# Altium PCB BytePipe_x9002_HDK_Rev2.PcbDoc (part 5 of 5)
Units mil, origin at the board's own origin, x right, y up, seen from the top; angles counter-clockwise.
Board outline 4250 x 4250 mil, 8 copper layers (Top Layer, L2-GND, L3-SIG, L4-GND, L5-PWR, L6-SIG, L7-GND, Bottom Layer), stack 63 mil thick; 296 components, 250 nets, 1198 pads, 2326 vias.
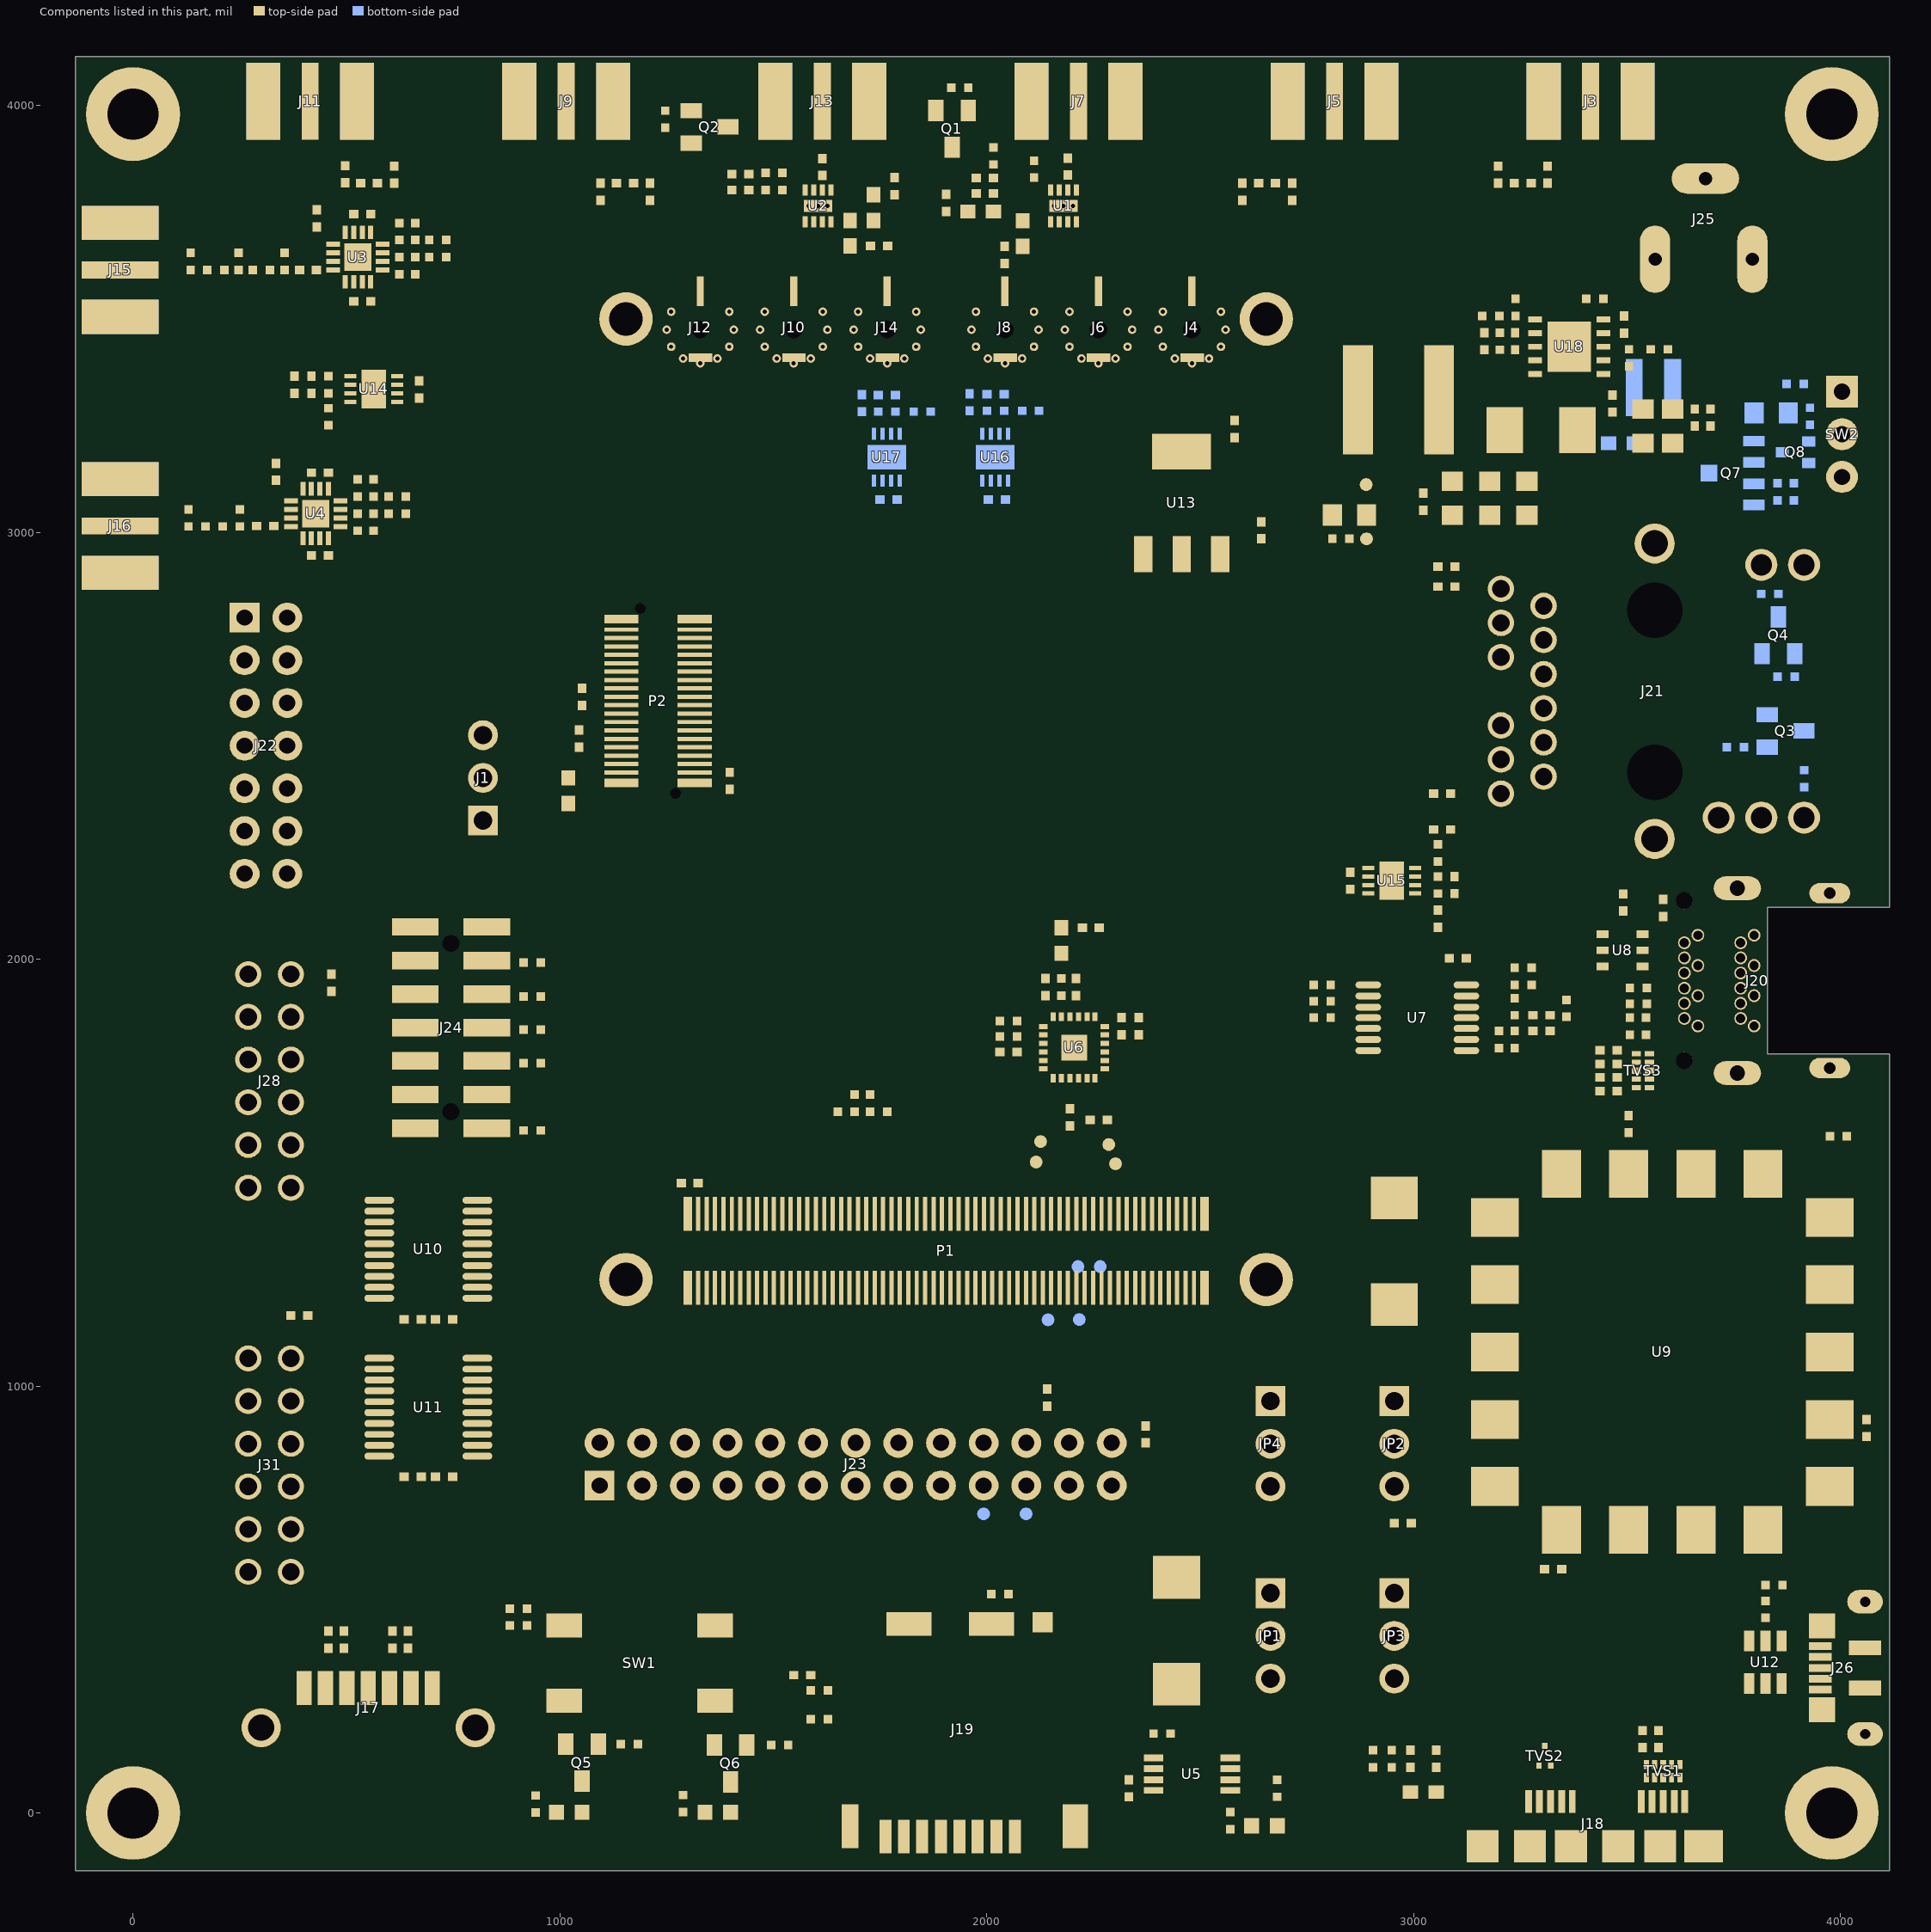
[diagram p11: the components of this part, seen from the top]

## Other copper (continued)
Bottom Layer:
  region net VCC5V0: 1761,3063.5 1761,3169 1731,3169 1731,3063.5
  region net VCC4V8_LNA1: 1757,3217 1757,3332 1735,3332 1735,3217
  region net VCC5V0: 2015,3069 2015,3169 1985,3169 1985,3069
  region net VCC4V8_LNA0: 2011,3217 2011,3334 1991,3334 1991,3217
  region net NetC73_2: 3607,3406 3711,3406 3711,3340 3643,3272 3607,3272
  text ".Layer_Name" at 2837.03,-378.88 h75

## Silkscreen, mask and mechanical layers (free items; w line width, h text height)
Top Overlay:
  drawing of 59 lines, arcs and shapes, not listed
  text "RX1B" at 3004,4048 h50
  text "RX2A" at 1248,4045 h50
  text "TX1" at 3604,4045 h50
  text "TX2" at 109,4040 h50
  text "RX1A" at 2408,4040 h50
  text "RX2B" at 658,4039 h50
  text "12V 2A" at 3659,3890 h40
  text "MCS" at -107,3803 h50
  text "ON" at 3771.5,3319.5 h40
  text "RF_CLK" at -117,3217 h50
  text "HDK_02" at 731.75,3188.74 h39.5 r270
  text "OFF" at 3770.5,3108.5 h40
  text "GND" at 83.5,2788.5 h30
  text "GND" at 438.5,2788.5 h30
  text "AUXADC_0" at -26.5,2689.5 h30
  text "AUXADC_1" at 436.5,2688.5 h30
  text "FAN" at 694.5,2600.5 h50
  text "GND" at 437.5,2586.5 h30
  text "GND" at 111.5,2584.5 h30
  text "RJ45 / ETHERNET" at 2853,2581 h35
  text "RFIC GPIO" at -94.5,2561 h50 r270
  text "AGPIO_2" at 432.5,2492.5 h30
  text "AGPIO_1" at 22.5,2484.5 h30
  text "AGPIO_4" at 433.5,2390.5 h30
  text "AGPIO_3" at 21.5,2385.5 h30
  text "AGPIO_6" at 432.5,2288.5 h30
  text "AGPIO_5" at 19.5,2285.5 h30
  text "DISPLAY" at 3832,2194 h50
  text "JTAG" at 657,2185 h50
  text "GND" at 433.5,2183.5 h30
  text "GND" at 112.5,2181.5 h30
  text "PMOD A" at -45.5,1309.5 h50
  text "UART1_RX" at 2005,935 h30 r90
  text "UART1_TX" at 1908,934 h30 r90
  text "GND" at 1107,932 h30 r90
  text "MIO43" at 1207.29,932 h30 r90
  text "MIO34" at 1307.57,932 h30 r90
  text "MIO42" at 1407.86,932 h30 r90
  text "MIO40" at 1508.14,932 h30 r90
  text "MIO44" at 1608.43,932 h30 r90
  text "MIO39" at 1708.71,932 h30 r90
  text "MIO41" at 1809,932 h30 r90
  text "GND" at 2208,932 h30 r90
  text "VCC3V3" at 2313,931 h30 r90
  text "VCC1V8" at 2107,930 h30 r90
  text "HOST" at 2882,923 h30 r90
  text "N/A" at 2585,922 h30 r90
  text "OTG" at 2587,747 h30 r90
  text "PWR SELECT" at 3089,707 h40 r90
  text "PS MIO" at 1023,704 h50 r90
  text "HRDW DETECT" at 2797,679 h40 r90
  text "OTG/ DEVICE" at 2881,639 h27 r90
  text "GND" at 2209,624 h30 r90
  text "MIO31" at 1307.5,597.78 h30 r90
  text "MIO36" at 1408,586.35 h30 r90
  text "MIO26" at 1609,586.35 h30 r90
  text "MIO32" at 1207,584.92 h30 r90
  text "MIO35" at 1508.5,584.92 h30 r90
  text "MIO33" at 1709.5,584.92 h30 r90
  text "MIO37" at 1810,584.92 h30 r90
  text "MIO38" at 1910.5,584.92 h30 r90
  text "GND" at 1107,577 h30 r90
  text "I2C_SCL" at 2105,563 h25 r90
  text "I2C_SDA" at 2006,561 h25 r90
  text "VCC3V3" at 2310,536 h30 r90
  text "SOM RESET" at 1066,505 h30
  text "OTG" at 2883,503 h30 r90
  text "SD CARD" at 2249,465 h50 r270
  text "JTAG Programmer" at 3246,423 h35
  text "OTG/ HOST" at 2592,419 h27 r90
  text "PMOD B" at -61.5,414.5 h50
  text "DEVICE" at 2591,241 h30 r90
  text "MODE SELECT" at 3091,223 h40 r90
  text "MODE SELECT" at 2798,220 h40 r90
  text "DEVICE/ HOST" at 2885,201 h27 r90
  text "SATA" at 154,117 h50 r90
  text "JTAG USB" at 3852,99 h50 r90
  text "PWR GOOD" at 1326,-103 h40
  text "PS DONE" at 956,-106 h40
  text "USB OVERCURRENT" at 2335,-110 h30
  text "USB  / 3.1-B" at 2916,-126 h45
  text ".Layer_Name" at 2837.03,-378.88 h75
Bottom Overlay:
  text ".Layer_Name" at 2837.03,-378.88 h75
Top Paste:
  text ".Layer_Name" at 2837.03,-378.88 h75
Bottom Paste:
  text ".Layer_Name" at 2837.03,-378.88 h75
Top Solder:
  text ".Layer_Name" at 2837.03,-378.88 h75
Bottom Solder:
  text ".Layer_Name" at 2837.03,-378.88 h75
Board Outline:
  the board outline again, w10
  text ".Layer_Name" at 2837.03,-378.88 h75
Sheet Graphics:
  drawing of 66 lines, arcs and shapes, not listed
  text "2" at 2433.03,6585.03 h180
  text "1" at 10933.03,6585.03 h180
  text "B" at -1624.97,4175.03 h280
  text "B" at 14755.03,4175.03 h280
  text "A" at 14726.03,-887.97 h280
  text "2130 Howard Drive W" at 2600,-1220 h75
  text "A" at -1624.97,-1324.97 h280
  text "North Mankato, MN 56003" at 2600,-1360 h75
  text "Reference Designs ARE PROVIDED \"AS IS\" AND \"WITH ALL FAULTS. / NextGen DISCLAIMS ALL OTHER WARRANTIES, EXPRESS OR IMPLIED,  / NextGen may make changes to specifications and product descriptions at / any time, without notice. The Customer must not REGARDING PRODUCTS,  / INCLUDING BUT NOT LIMITED TO, ANY IMPLIED WARRANTIES OF / MERCHANTABILITY OR FITNESS FOR A PARTICULAR PURPOSE rely on / the absence or characteristics of any features or instructions marked / \"reserved\" or \"undefined.\"  NextGen reserves these for future definition and / shall have no responsibility whatsoever for conflicts or incompatibilities  / arising from future changes to them. The product information on the Web / Site or Materials is subject to change without notice. Do not finalize a / design with this information." at -240,-1400 h40 r0.2
  text "NextGen RF Design, Inc." at 12660,-2125 h100
  text "2130 Howard Drive W" at 12652.03,-2309.15 h100
  text "North Mankato, MN 56003" at 12652.03,-2470.97 h100
  text "NEXTGEN RF DESIGN" at 11632.03,-2707.97 h100
  text "RF SOM" at 11626.03,-2849.97 h100
  text "Reference Designs ARE PROVIDED \"AS IS\" AND \"WITH ALL FAULTS. / NextGen DISCLAIMS ALL OTHER WARRANTIES, EXPRESS OR IMPLIED,  / NextGen may make changes to specifications and product descriptions at / any time, without notice. The Customer must not REGARDING PRODUCTS,  / INCLUDING BUT NOT LIMITED TO, ANY IMPLIED WARRANTIES OF / MERCHANTABILITY OR FITNESS FOR A PARTICULAR PURPOSE rely on / the absence or characteristics of any features or instructions marked / \"reserved\" or \"undefined.\"  NextGen reserves these for future definition and / shall have no responsibility whatsoever for conflicts or incompatibilities  / arising from future changes to them. The product information on the Web / Site or Materials is subject to change without notice. Do not finalize a / design with this information." at 8160,-2855 h40 r0.2
  text "ENGINEER" at 8343.03,-2954.97 h50
  text "ELLIOTT NELSON" at 9003.03,-2994.97 h50
  text "BYTEPIPE HARDWARE DEVELOPMENT KIT" at 11634.03,-2994.97 h100
  text "PCB DESIGNER" at 8343.03,-3154.97 h50
  text "SIZE" at 10443.03,-3154.97 h50
  text "CAGE NO." at 10763.03,-3154.97 h50
  text "CAD GENERATED:" at 11860.03,-3154.97 h50
  text "REV." at 14303.03,-3154.97 h50
  text "MIKE LARSEN" at 9003.03,-3194.97 h50
  text "\".pcb_File_Name_No_Path\"" at 11969.03,-3297.97 h85.63
  text "DATE" at 8343.03,-3334.97 h50
  text "B" at 10463.03,-3334.97 h100
  text "2" at 14303.03,-3334.97 h100
  text ".Print_Date" at 9003.03,-3374.97 h50
  text ".Print_Scale" at 10363.03,-3594.97 h50
  text "SHEET:" at 12863.03,-3594.97 h50
  text "1 OF 1" at 13593.03,-3594.97 h50
  text "2" at 2433.03,-3849.97 h180
  text "1" at 10933.03,-3849.97 h180
Gerber Title Block:
  lines w15: -280,-480 4240,-480 ; -280,-180 4240,-180 ; 1960,-1460 1960,-180
  lines w30: -280,-1460 4240,-1460 4240,4200 4240,4240 -280,4240 -280,-1460
  text "Project : BYTEPIPE Hardware Dev Kit" at -210,-365.01 h75
  text "Gerber Layer :" at 2070,-365.01 h75
Drill Drawing:
  drawing of 663 lines, arcs and shapes, not listed
  text "FABRICATION NOTES: /  / 1. MATERIALS: /    ISOLA 370HR with 1/2 oz starting Copper and 1oz. copper plating. /        / 2. Board is 8 layers, finished board thickness = .062\" +/- 10%. /    Shall conform to IPC-2221, UL 94V-0 and European Directive 2011/65/EC (ROHS2). /     / 3. Finished board shall meet requirements of IPC-A-600. /    Finished trace width and outer diameter of plated holes shall be /    within .001\" or less of image on photo tool master. /    Annular rings to meet IPC-600J class 2. /     / 4. Holes to be plated through in accordance with IPC-600J. /     Dimensions shown are for finished plated through holes. /      / 5. All exposed copper to be finished with ENIG, as per IPC-4552.  /  / 6. Screen legend with white non-conductive ink, both sides. Contact areas of SMT components to be free of ink. /      / 7. SMOBC: BLACK LPI solder mask. Both sides. /     / 8. Board to be 100% bare board tested and report provided. /  / 9. Design rules used: 5mil trace, 5mil space. /  / 10. Plated holes have a +/- 0.003 inch tolerance. /     Non-plated +/- 0.0015 unless otherwise specified /  / 11.   DO NOT adjust Stack-up or Trace widthes without contacting NEXTGEN RF." at 5655,-165 h80
  text ".Layer_Name" at 1162.89,-331.24 h100
  text "DRILL TABLE" at 725,-540 h100
  text "LAYER STACK" at 5281,-571 h100
  text "Symbol" at -575.47,-792.27 h53.62
  text "Count" at -242.53,-792.27 h53.62
  text "Hole Size" at 162.11,-792.27 h53.62
  text "Plated" at 899.9,-792.27 h53.62
  text "Hole Type" at 1187.66,-792.27 h53.62
  text "Drill Layer Pair" at 1618.64,-792.27 h53.62
  text "Via/Pad" at 2531.71,-792.27 h53.62
  text "Layer" at 3573.3,-876.99 h58.23
  text "Name" at 3971.72,-876.99 h58.23
  text "Material" at 4874.66,-876.99 h58.23
  text "Thickness" at 5709.67,-876.99 h58.23
  text "Constant" at 6340.95,-876.99 h58.23
  text "Board Layer Stack" at 6894.61,-876.99 h58.23
  text "307" at -242.53,-903.98 h44.68
  text "8.00mil (0.203mm)" at 162.11,-903.98 h44.68
  text "PTH" at 899.9,-903.98 h44.68
  text "Round" at 1187.66,-903.98 h44.68
  text "Top Layer - Bottom Layer" at 1618.64,-903.98 h44.68
  text "Via" at 2531.71,-903.98 h44.68
  text "Top Overlay" at 3971.72,-993.46 h58.23
  text "1980" at -242.53,-1015.69 h44.68
  text "8.00mil (0.203mm)" at 162.11,-1015.69 h44.68
  text "PTH" at 899.9,-1015.69 h44.68
  text "Round" at 1187.66,-1015.69 h44.68
  text "Top Layer - Bottom Layer" at 1618.64,-1015.69 h44.68
  text "Via" at 2531.71,-1015.69 h44.68
  text "Top Solder" at 3971.72,-1109.92 h58.23
  text "Solder Resist" at 4874.66,-1109.92 h58.23
  text "0.40mil" at 5709.67,-1109.92 h58.23
  text "3.5" at 6340.95,-1109.92 h58.23
  text "39" at -242.53,-1127.4 h44.68
  text "10.00mil (0.254mm)" at 162.11,-1127.4 h44.68
  text "PTH" at 899.9,-1127.4 h44.68
  text "Round" at 1187.66,-1127.4 h44.68
  text "Top Layer - Bottom Layer" at 1618.64,-1127.4 h44.68
  text "Via" at 2531.71,-1127.4 h44.68
  text "H" at -595.46,-1132.39 h49.65
  text "1" at 3573.3,-1226.39 h58.23
  text "Top Layer" at 3971.72,-1226.39 h58.23
  text "CF-003" at 4874.66,-1226.39 h58.23
  text "1.40mil" at 5709.67,-1226.39 h58.23
  text "60" at -242.53,-1239.11 h44.68
  text "10.00mil (0.254mm)" at 162.11,-1239.11 h44.68
  text "PTH" at 899.9,-1239.11 h44.68
  text "Round" at 1187.66,-1239.11 h44.68
  text "Top Layer - Bottom Layer" at 1618.64,-1239.11 h44.68
  text "Pad" at 2531.71,-1239.11 h44.68
  text "Dielectric 1" at 3971.72,-1342.85 h58.23
  text "370HR" at 4874.66,-1342.85 h58.23
  text "8.00mil" at 5709.67,-1342.85 h58.23
  text "4" at 6340.95,-1342.85 h58.23
  text "20" at -242.53,-1350.82 h44.68
  text "22.00mil (0.559mm)" at 162.11,-1350.82 h44.68
  text "PTH" at 899.9,-1350.82 h44.68
  text "Round" at 1187.66,-1350.82 h44.68
  text "Top Layer - Bottom Layer" at 1618.64,-1350.82 h44.68
  text "Pad" at 2531.71,-1350.82 h44.68
  text "C" at -595.46,-1355.81 h49.65
  text "2" at 3573.3,-1459.31 h58.23
  text "L2-GND" at 3971.72,-1459.31 h58.23
  text "CF-004" at 4874.66,-1459.31 h58.23
  text "0.70mil" at 5709.67,-1459.31 h58.23
  text "2" at -242.53,-1462.53 h44.68
  text "24.00mil (0.610mm)" at 162.11,-1462.53 h44.68
  text "PTH" at 899.9,-1462.53 h44.68
  text "Slot" at 1187.66,-1462.53 h44.68
  text "Top Layer - Bottom Layer" at 1618.64,-1462.53 h44.68
  text "Pad" at 2531.71,-1462.53 h44.68
  text "B" at -595.46,-1467.52 h49.65
  text "2" at -242.53,-1574.24 h44.68
  text "25.59mil (0.650mm)" at 162.11,-1574.24 h44.68
  text "NPTH" at 899.9,-1574.24 h44.68
  text "Round" at 1187.66,-1574.24 h44.68
  text "Top Layer - Bottom Layer" at 1618.64,-1574.24 h44.68
  text "Pad" at 2531.71,-1574.24 h44.68
  text "Dielectric 2" at 3971.72,-1575.78 h58.23
  text "370HR" at 4874.66,-1575.78 h58.23
  text "8.00mil" at 5709.67,-1575.78 h58.23
  text "4" at 6340.95,-1575.78 h58.23
  text "2" at -242.53,-1685.95 h44.68
  text "27.56mil (0.700mm)" at 162.11,-1685.95 h44.68
  text "PTH" at 899.9,-1685.95 h44.68
  text "Slot" at 1187.66,-1685.95 h44.68
  text "Top Layer - Bottom Layer" at 1618.64,-1685.95 h44.68
  text "Pad" at 2531.71,-1685.95 h44.68
  text "3" at 3573.3,-1692.24 h58.23
  text "L3-SIG" at 3971.72,-1692.24 h58.23
  text "CF-004" at 4874.66,-1692.24 h58.23
  text "0.70mil" at 5709.67,-1692.24 h58.23
  text "3" at -242.53,-1797.66 h44.68
  text "31.00mil (0.787mm)" at 162.11,-1797.66 h44.68
  text "PTH" at 899.9,-1797.66 h44.68
  text "Slot" at 1187.66,-1797.66 h44.68
  text "Top Layer - Bottom Layer" at 1618.64,-1797.66 h44.68
  text "Pad" at 2531.71,-1797.66 h44.68
  text "Dielectric 3" at 3971.72,-1808.7 h58.23
  text "370HR" at 4874.66,-1808.7 h58.23
  text "8.00mil" at 5709.67,-1808.7 h58.23
  text "4" at 6340.95,-1808.7 h58.23
  text "2" at -242.53,-1909.37 h44.68
  text "35.43mil (0.900mm)" at 162.11,-1909.37 h44.68
  text "PTH" at 899.9,-1909.37 h44.68
  text "Slot" at 1187.66,-1909.37 h44.68
  text "Top Layer - Bottom Layer" at 1618.64,-1909.37 h44.68
  text "Pad" at 2531.71,-1909.37 h44.68
  text "4" at 3573.3,-1925.17 h58.23
  text "L4-GND" at 3971.72,-1925.17 h58.23
  text "CF-004" at 4874.66,-1925.17 h58.23
  text "0.70mil" at 5709.67,-1925.17 h58.23
  text "43" at -242.53,-2021.08 h44.68
  text "38.00mil (0.965mm)" at 162.11,-2021.08 h44.68
  text "PTH" at 899.9,-2021.08 h44.68
  text "Round" at 1187.66,-2021.08 h44.68
  text "Top Layer - Bottom Layer" at 1618.64,-2021.08 h44.68
  text "Pad" at 2531.71,-2021.08 h44.68
  text "Dielectric 4" at 3971.72,-2041.63 h58.23
  text "370HR" at 4874.66,-2041.63 h58.23
  text "8.00mil" at 5709.67,-2041.63 h58.23
  text "4" at 6340.95,-2041.63 h58.23
  text "4" at -242.53,-2132.79 h44.68
  text "40.00mil (1.016mm)" at 162.11,-2132.79 h44.68
  text "NPTH" at 899.9,-2132.79 h44.68
  text "Round" at 1187.66,-2132.79 h44.68
  text "Top Layer - Bottom Layer" at 1618.64,-2132.79 h44.68
  text "Pad" at 2531.71,-2132.79 h44.68
  text "A" at -595.46,-2137.78 h49.65
  text "5" at 3573.3,-2158.09 h58.23
  text "L5-PWR" at 3971.72,-2158.09 h58.23
  text "CF-004" at 4874.66,-2158.09 h58.23
  text "0.70mil" at 5709.67,-2158.09 h58.23
  text "24" at -242.53,-2244.5 h44.68
  text "40.95mil (1.040mm)" at 162.11,-2244.5 h44.68
  text "PTH" at 899.9,-2244.5 h44.68
  text "Round" at 1187.66,-2244.5 h44.68
  text "Top Layer - Bottom Layer" at 1618.64,-2244.5 h44.68
  text "Pad" at 2531.71,-2244.5 h44.68
  text "Dielectric 5" at 3971.72,-2274.56 h58.23
  text "370HR" at 4874.66,-2274.56 h58.23
  text "8.00mil" at 5709.67,-2274.56 h58.23
  text "4" at 6340.95,-2274.56 h58.23
  text "6" at -242.53,-2356.21 h44.68
  text "41.00mil (1.041mm)" at 162.11,-2356.21 h44.68
  text "NPTH" at 899.9,-2356.21 h44.68
  text "Round" at 1187.66,-2356.21 h44.68
  text "Top Layer - Bottom Layer" at 1618.64,-2356.21 h44.68
  text "Pad" at 2531.71,-2356.21 h44.68
  text "G" at -595.46,-2361.2 h49.65
  text "6" at 3573.3,-2391.02 h58.23
  text "L6-SIG" at 3971.72,-2391.02 h58.23
  text "CF-004" at 4874.66,-2391.02 h58.23
  text "0.70mil" at 5709.67,-2391.02 h58.23
  text "12" at -242.53,-2467.92 h44.68
  text "41.00mil (1.041mm)" at 162.11,-2467.92 h44.68
  text "PTH" at 899.9,-2467.92 h44.68
  text "Round" at 1187.66,-2467.92 h44.68
  text "Top Layer - Bottom Layer" at 1618.64,-2467.92 h44.68
  text "Pad" at 2531.71,-2467.92 h44.68
  text "D" at -595.46,-2472.91 h49.65
  text "Dielectric 6" at 3971.72,-2507.48 h58.23
  text "370HR" at 4874.66,-2507.48 h58.23
  text "8.00mil" at 5709.67,-2507.48 h58.23
  text "4" at 6340.95,-2507.48 h58.23
  text "15" at -242.53,-2579.63 h44.68
  text "43.00mil (1.092mm)" at 162.11,-2579.63 h44.68
  text "PTH" at 899.9,-2579.63 h44.68
  text "Round" at 1187.66,-2579.63 h44.68
  text "Top Layer - Bottom Layer" at 1618.64,-2579.63 h44.68
  text "Pad" at 2531.71,-2579.63 h44.68
  text "7" at 3573.3,-2623.95 h58.23
  text "L7-GND" at 3971.72,-2623.95 h58.23
  text "CF-004" at 4874.66,-2623.95 h58.23
  text "0.70mil" at 5709.67,-2623.95 h58.23
  text "5" at -242.53,-2691.34 h44.68
  text "50.00mil (1.270mm)" at 162.11,-2691.34 h44.68
  text "PTH" at 899.9,-2691.34 h44.68
  text "Round" at 1187.66,-2691.34 h44.68
  text "Top Layer - Bottom Layer" at 1618.64,-2691.34 h44.68
  text "Pad" at 2531.71,-2691.34 h44.68
  text "Dielectric 7" at 3971.72,-2740.41 h58.23
  text "370HR" at 4874.66,-2740.41 h58.23
  text "8.00mil" at 5709.67,-2740.41 h58.23
  text "4" at 6340.95,-2740.41 h58.23
  text "2" at -242.53,-2803.05 h44.68
  text "61.02mil (1.550mm)" at 162.11,-2803.05 h44.68
  text "PTH" at 899.9,-2803.05 h44.68
  text "Round" at 1187.66,-2803.05 h44.68
  text "Top Layer - Bottom Layer" at 1618.64,-2803.05 h44.68
  text "Pad" at 2531.71,-2803.05 h44.68
  text "8" at 3573.3,-2856.88 h58.23
  text "Bottom Layer" at 3971.72,-2856.88 h58.23
  text "CF-003" at 4874.66,-2856.88 h58.23
  text "1.40mil" at 5709.67,-2856.88 h58.23
  text "2" at -242.53,-2914.76 h44.68
  text "62.00mil (1.575mm)" at 162.11,-2914.76 h44.68
  text "PTH" at 899.9,-2914.76 h44.68
  text "Round" at 1187.66,-2914.76 h44.68
  text "Top Layer - Bottom Layer" at 1618.64,-2914.76 h44.68
  text "Pad" at 2531.71,-2914.76 h44.68
  text "E" at -595.46,-2919.75 h49.65
  text "Bottom Solder" at 3971.72,-2973.34 h58.23
  text "Solder Resist" at 4874.66,-2973.34 h58.23
  text "0.40mil" at 5709.67,-2973.34 h58.23
  text "3.5" at 6340.95,-2973.34 h58.23
  text "4" at -242.53,-3026.47 h44.68
  text "78.00mil (1.981mm)" at 162.11,-3026.47 h44.68
  text "PTH" at 899.9,-3026.47 h44.68
  text "Round" at 1187.66,-3026.47 h44.68
  text "Top Layer - Bottom Layer" at 1618.64,-3026.47 h44.68
  text "Pad" at 2531.71,-3026.47 h44.68
  text "Bottom Overlay" at 3971.72,-3089.8 h58.23
  text "4" at -242.53,-3138.18 h44.68
  text "120.00mil (3.048mm)" at 162.11,-3138.18 h44.68
  text "PTH" at 899.9,-3138.18 h44.68
  text "Round" at 1187.66,-3138.18 h44.68
  text "Top Layer - Bottom Layer" at 1618.64,-3138.18 h44.68
  text "Pad" at 2531.71,-3138.18 h44.68
  text "2" at -242.53,-3249.89 h44.68
  text "130.00mil (3.302mm)" at 162.11,-3249.89 h44.68
  text "NPTH" at 899.9,-3249.89 h44.68
  text "Round" at 1187.66,-3249.89 h44.68
  text "Top Layer - Bottom Layer" at 1618.64,-3249.89 h44.68
  text "Pad" at 2531.71,-3249.89 h44.68
  text "F" at -595.46,-3254.88 h49.65
  text "2540 Total" at -242.53,-3361.6 h44.68
  text "Slot definitions :" at -575.47,-3464.68 h44.68
  text "Routed Path Length" at -34.63,-3464.68 h44.68
  text "= Calculated from tool start centre position to tool end centre position." at 611.95,-3464.68 h44.68
  text "Hole Length" at -34.63,-3534.24 h44.68
  text "= Routed Path Length + Tool Size = Slot length as defined in the PCB layout" at 356.88,-3534.24 h44.68

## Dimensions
-135,4115 to -135,-135 on Fab/Dimensions
-135,4115 to 4115,4115 on Fab/Dimensions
